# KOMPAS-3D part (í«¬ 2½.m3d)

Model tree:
1. Эскиз:1
2. Операция выдавливания:1
     Расстояние 1 = 2
3. Эскиз:2
4. Операция выдавливания:2
     Расстояние 1 = 5
5. Эскиз:3
6. Операция выдавливания:3
     Расстояние 1 = 2
7. Эскиз:4
8. Операция выдавливания:4
     Расстояние 1 = 60
9. Эскиз:5
10. Операция выдавливания:5
     Расстояние 1 = 2
11. Эскиз:6
12. Операция выдавливания:6
     Расстояние 1 = 4.5
13. Эскиз:7
14. Операция выдавливания:7
     Расстояние 1 = 2
15. Скругление:1
     Радиус = 1
16. Скругление:2
     Радиус = 1
17. Эскиз:8
18. Вырезать элемент выдавливания:1
     Расстояние 1 = 10; Угол 1 = 35
19. Эскиз:9
20. Вырезать элемент выдавливания:2
     Расстояние 1 = 10; Угол 1 = 35
21. Эскиз:10
22. Вырезать элемент выдавливания:3
     Расстояние 2 = 22; Расстояние 1 = 22; Угол 1 = 35
23. Эскиз:11
24. Вырезать элемент выдавливания:4
     Расстояние 2 = 2; Расстояние 1 = 2
25. Эскиз:12
26. Вырезать элемент выдавливания:5
     Расстояние 2 = 2; Расстояние 1 = 2; Угол 1 = 35
27. Эскиз:13
28. Вырезать элемент выдавливания:6
     Расстояние 2 = 2; Расстояние 1 = 122
29. Эскиз:15
30. Операция выдавливания:9
     Расстояние 1 = 10; Расстояние 2 = 0.5
